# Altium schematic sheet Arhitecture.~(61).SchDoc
size A3; SheetNumber: 1; SheetTotal: 5
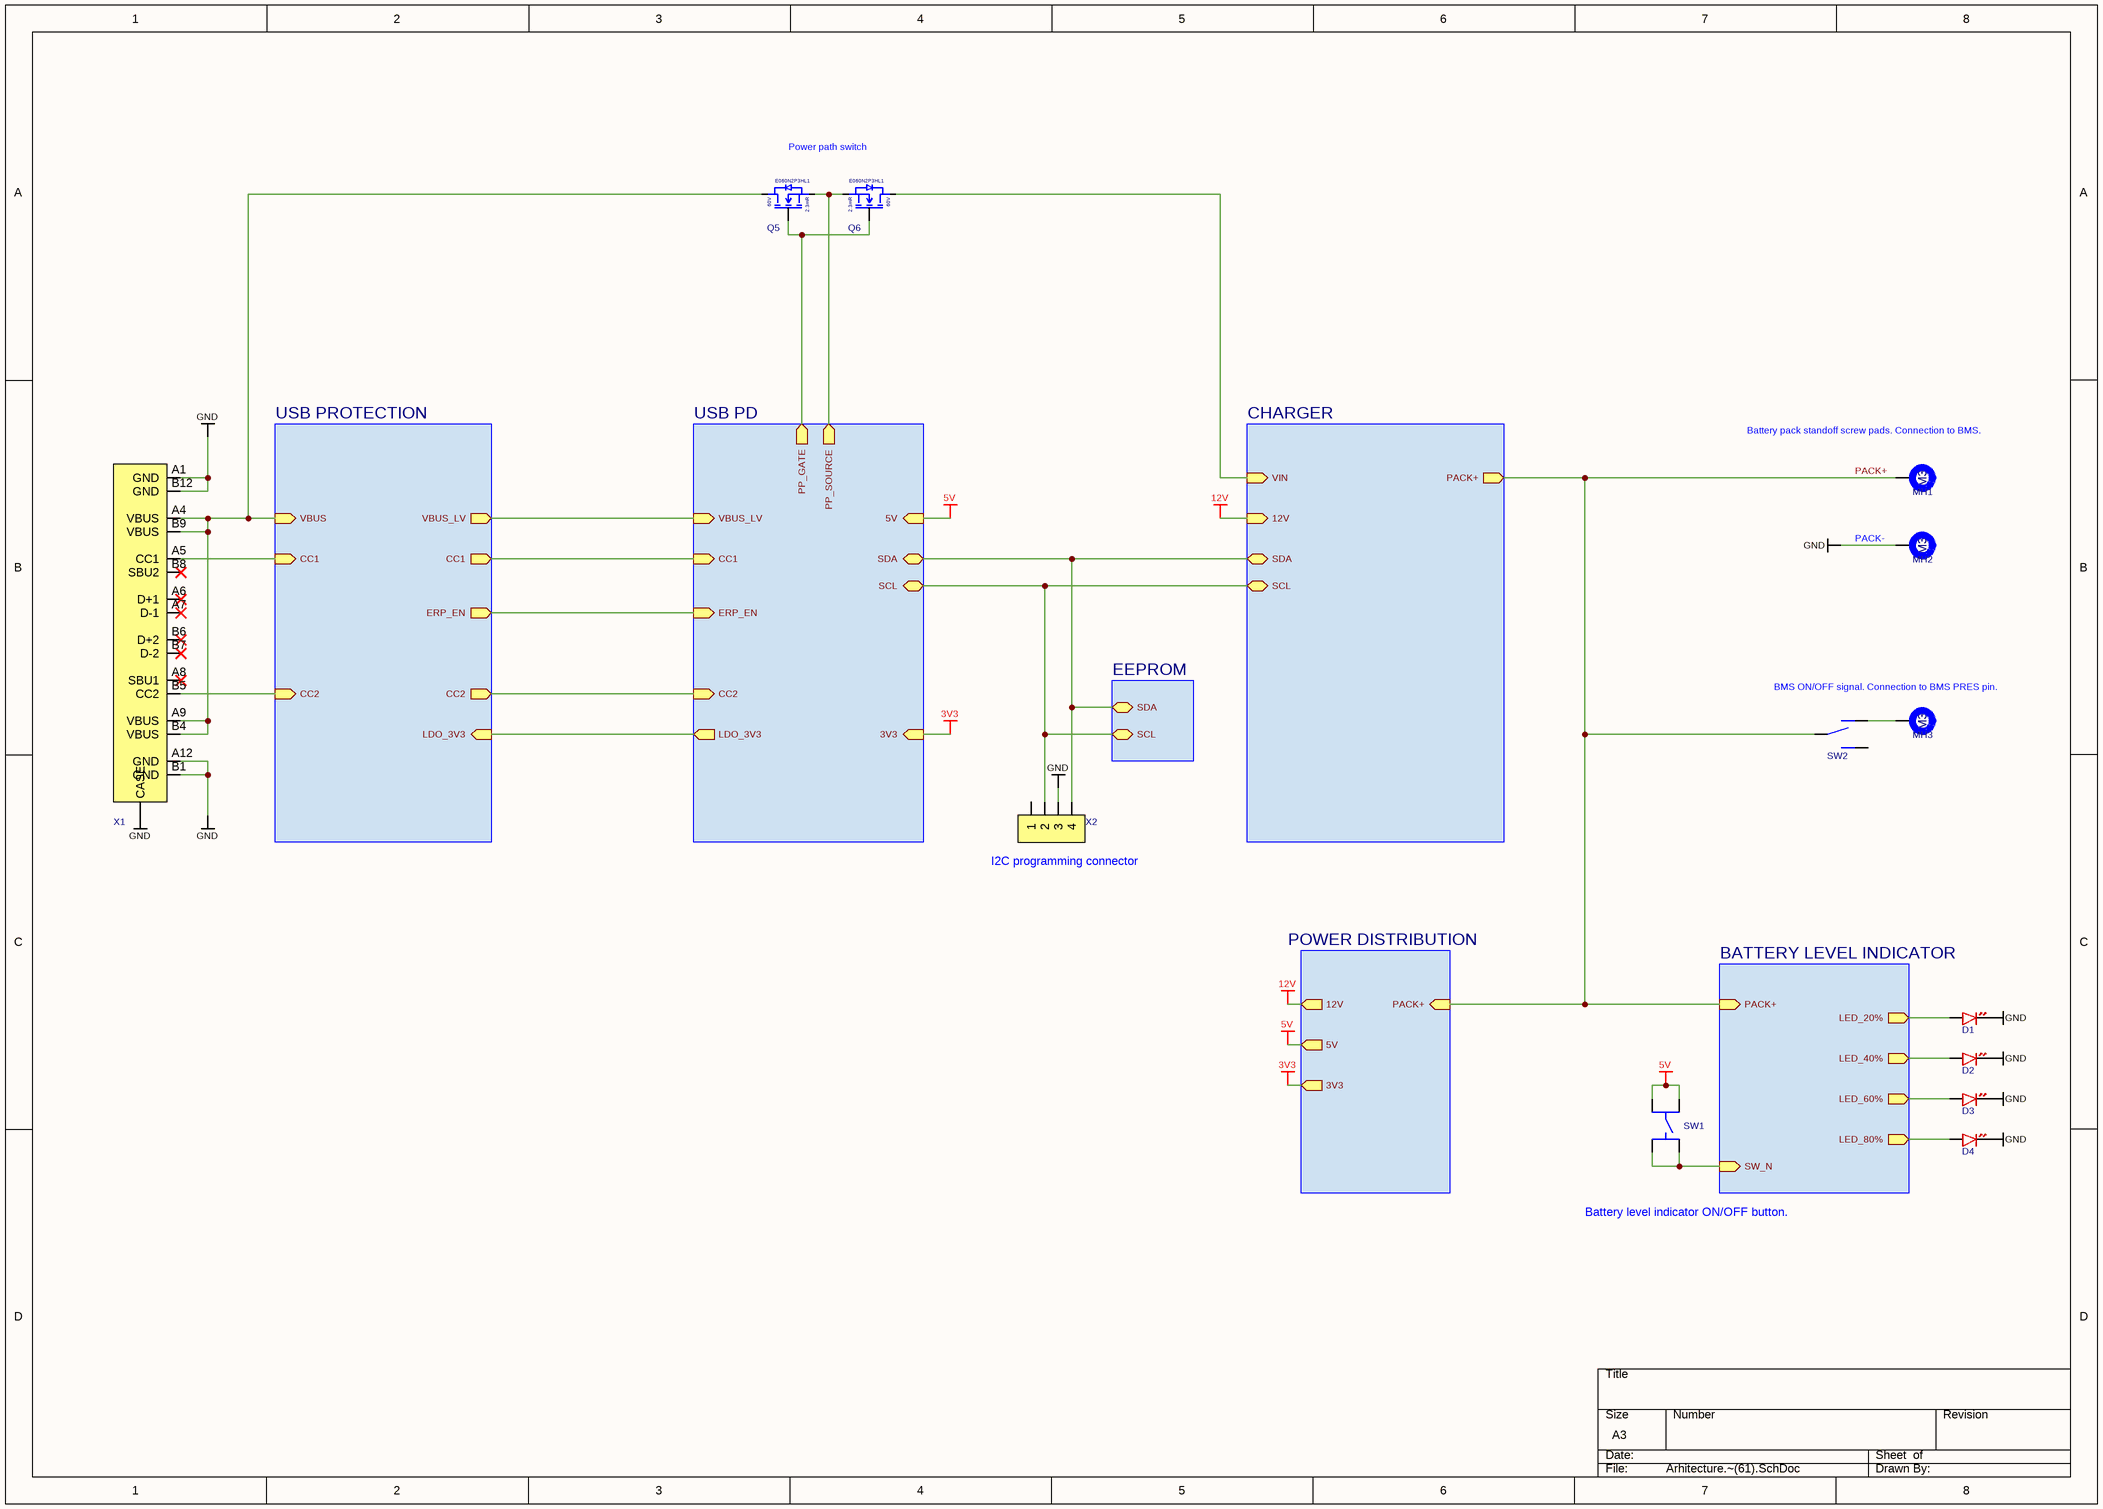
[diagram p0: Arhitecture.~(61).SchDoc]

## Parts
D1  XL-1608SURC-06  [DIODE_0603]  (value not drawn)
D2  XL-1608SURC-06  [DIODE_0603]  (value not drawn)
D3  XL-1608SURC-06  [DIODE_0603]  (value not drawn)
D4  XL-1608SURC-06  [DIODE_0603]  (value not drawn)
MH1  Hole size: M3  [M3 Plated]  (hidden comment: M?)  (no BOM)
MH2  Hole size: M3  [M3 Plated]  (hidden comment: M?)  (no BOM)
MH3  Hole size: M3  [M3 Plated]  (hidden comment: M?)  (no BOM)
Q5  Rds: 2.3mR  Voltage: 60V  [DFN-8 (5x6)]  (hidden comment: E060N2P3HL1)
Q6  Rds: 2.3mR  Voltage: 60V  [DFN-8 (5x6)]  (hidden comment: E060N2P3HL1)
SW1  TS4560TP  [TS4560TP]  (value not drawn)
SW2  SS-3235S-L3  [SS-3235S-L3]  (value not drawn)
X1  TYPE-C 16P LTH6.8  [TYPE-C 16P LTH6.8]  (value not drawn)
X2  B4B-PH-K-S(LF)(SN)  [B4B-PH-K-S(LF)(SN)]  (value not drawn)

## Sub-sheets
BATTERY LEVEL INDICATOR = Battery level indicator.SchDoc: PACK+ (in), SW_N (in), LED_20% (out), LED_40% (out), LED_60% (out), LED_80% (out)
CHARGER = Charger.SchDoc: PACK+ (out), VIN (in), SDA (bidir), SCL (bidir), 12V (in)
EEPROM = EEPROM.SchDoc: SDA (bidir), SCL (bidir)
POWER DISTRIBUTION = Power distribution.SchDoc: PACK+ (in), 12V (out), 5V (out), 3V3 (out)
USB PD = USB PD.SchDoc: VBUS_LV (in), ERP_EN (in), CC1 (in), LDO_3V3 (out), PP_GATE (out), PP_SOURCE (out), SDA (bidir), SCL (bidir), 5V (in), 3V3 (in), CC2 (in)
USB PROTECTION = USB protection.SchDoc: VBUS (in), CC1 (in), CC2 (in), VBUS_LV (out), ERP_EN (out), CC1 (out), LDO_3V3 (in), CC2 (out)

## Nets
3V3: sheet POWER DISTRIBUTION/3V3, sheet USB PD/3V3
5V: SW1.1 SW1.2 ; sheet POWER DISTRIBUTION/5V, sheet USB PD/5V
12V: sheet CHARGER/12V, sheet POWER DISTRIBUTION/12V
GND: D1.K D2.K D3.K D4.K MH2.1 X1.A1(GND) X1.A12(GND) X1.B1(GND) X1.B12(GND) X1.CASE X2.3
PACK+: MH1.1 SW2.2 ; sheet CHARGER/PACK+, sheet POWER DISTRIBUTION/PACK+, sheet BATTERY LEVEL INDICATOR/PACK+
NetD1_A: D1.A ; sheet BATTERY LEVEL INDICATOR/LED_20%
NetD2_A: D2.A ; sheet BATTERY LEVEL INDICATOR/LED_40%
NetD3_A: D3.A ; sheet BATTERY LEVEL INDICATOR/LED_60%
NetD4_A: D4.A ; sheet BATTERY LEVEL INDICATOR/LED_80%
NetMH3_1: MH3.1 SW2.1
NetQ5_D: Q5.D X1.A4(VBUS) X1.A9(VBUS) X1.B4(VBUS) X1.B9(VBUS) ; sheet USB PROTECTION/VBUS
NetQ5_G: Q5.G Q6.G ; sheet USB PD/PP_GATE
NetQ5_S: Q5.S Q6.S ; sheet USB PD/PP_SOURCE
NetQ6_D: Q6.D ; sheet CHARGER/VIN
NetSW1_3: SW1.3 SW1.4 ; sheet BATTERY LEVEL INDICATOR/SW_N
NetX1_A5: X1.A5(CC1) ; sheet USB PROTECTION/CC1
NetX1_B5: X1.B5(CC2) ; sheet USB PROTECTION/CC2
NetX2_2: X2.2 ; sheet CHARGER/SCL, sheet EEPROM/SCL, sheet USB PD/SCL
NetX2_4: X2.4 ; sheet CHARGER/SDA, sheet EEPROM/SDA, sheet USB PD/SDA
(unnamed): sheet USB PD/VBUS_LV, sheet USB PROTECTION/VBUS_LV
(unnamed): sheet USB PD/ERP_EN, sheet USB PROTECTION/ERP_EN  [a separate net that carries the same name]
(unnamed): sheet USB PD/CC1, sheet USB PROTECTION/CC1  [a separate net that carries the same name]
(unnamed): sheet USB PD/LDO_3V3, sheet USB PROTECTION/LDO_3V3  [a separate net that carries the same name]
(unnamed): sheet USB PD/CC2, sheet USB PROTECTION/CC2  [a separate net that carries the same name]

Not connected (* = marked no-connect by the designer): SW2 3; X1 A6(D+1)* A7(D-1)* A8(SBU1)* B6(D+2)* B7(D-2)* B8(SBU2)*; X2 1

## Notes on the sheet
- Power path switch
- (near MH1) Battery pack standoff screw pads. Connection to BMS.
- (near MH2) PACK-
- BMS ON/OFF signal. Connection to BMS PRES pin.
- (near X2) I2C programming connector
- Battery level indicator ON/OFF button.

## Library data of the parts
D1-D4 = XL-1608SURC-06: LED Red 0603 25mA; Manufacturer: Xinglight
MH1-MH3 = Mounting hole: Generic mounting hole symbol
Q5 Q6 = E060N2P3HL1: Nmos 60V 180A 2.3mR PDFN5x6-8; Manufacturer: Existar
SW1 = TS4560TP: Switch Tactile SMD 4.5x4.5mm 6mmH SPST; Manufacturer: Shou Han
SW2 = SS-3235S-L3: Switch Slide SMD 9.1x3.5mm 6.6mmH; Manufacturer: XKB Connection
X1 = TYPE-C 16P LTH6.8: USB-C 16P SMD Vertical 6.50mmH; Manufacturer: Shou Han
X2 = B4B-PH-K-S(LF)(SN): Pin header 1x4 2.00mmP THT Vertical JST PH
